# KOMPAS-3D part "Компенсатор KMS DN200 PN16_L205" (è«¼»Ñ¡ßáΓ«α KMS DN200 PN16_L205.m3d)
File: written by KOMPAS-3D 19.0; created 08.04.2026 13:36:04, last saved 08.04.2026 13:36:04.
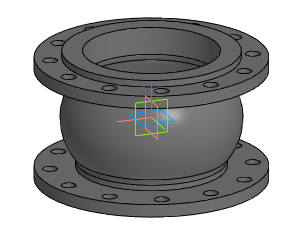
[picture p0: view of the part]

Document properties: Автор: Энергия; Полное имя файла: Z:\3.Личные\kachalov\3d для проектировщиков\7.1 Компенсатор\stp_Компенсатор KSM\Компенсатор KMS DN200 PN16_L205.m3d

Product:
- Part/product: Компенсатор KMS DN200 PN16_L205

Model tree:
1. Операция без истории:1  (labels: Компенсатор KMS DN200 PN16_L205)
